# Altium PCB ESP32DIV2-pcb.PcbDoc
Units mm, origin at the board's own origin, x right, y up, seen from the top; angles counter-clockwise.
Board outline 52.58 x 99.94 mm, 2 copper layers (Top Layer, Bottom Layer); 90 components, 85 nets, 423 pads, 138 vias.
Unrouted connection lines stored in the file: 11.
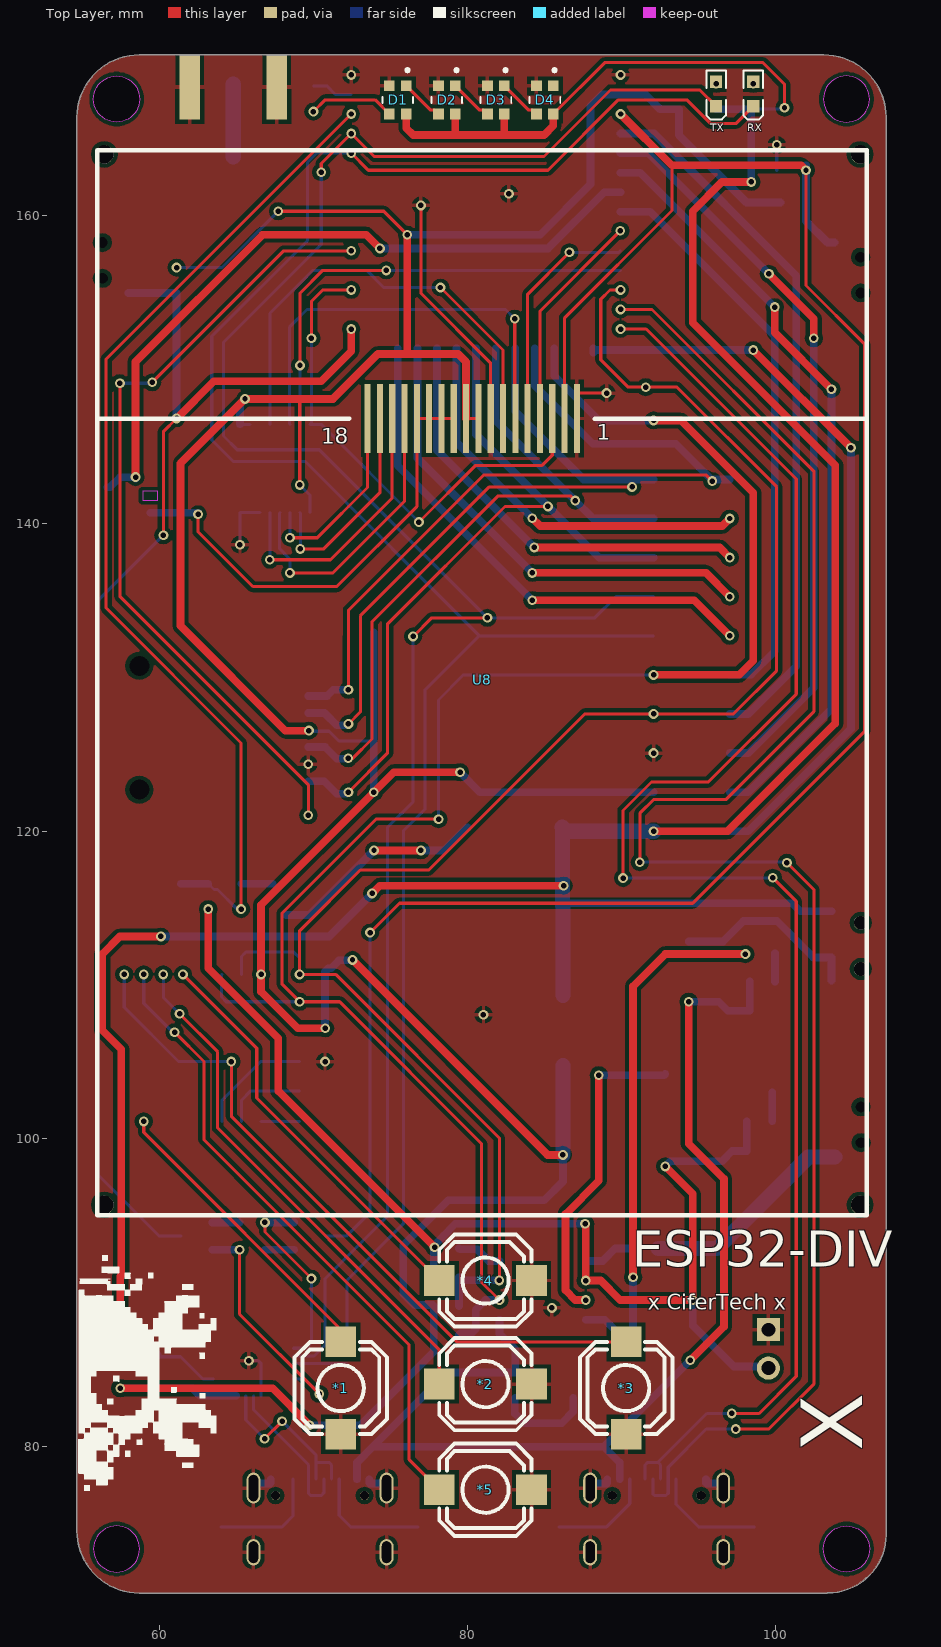
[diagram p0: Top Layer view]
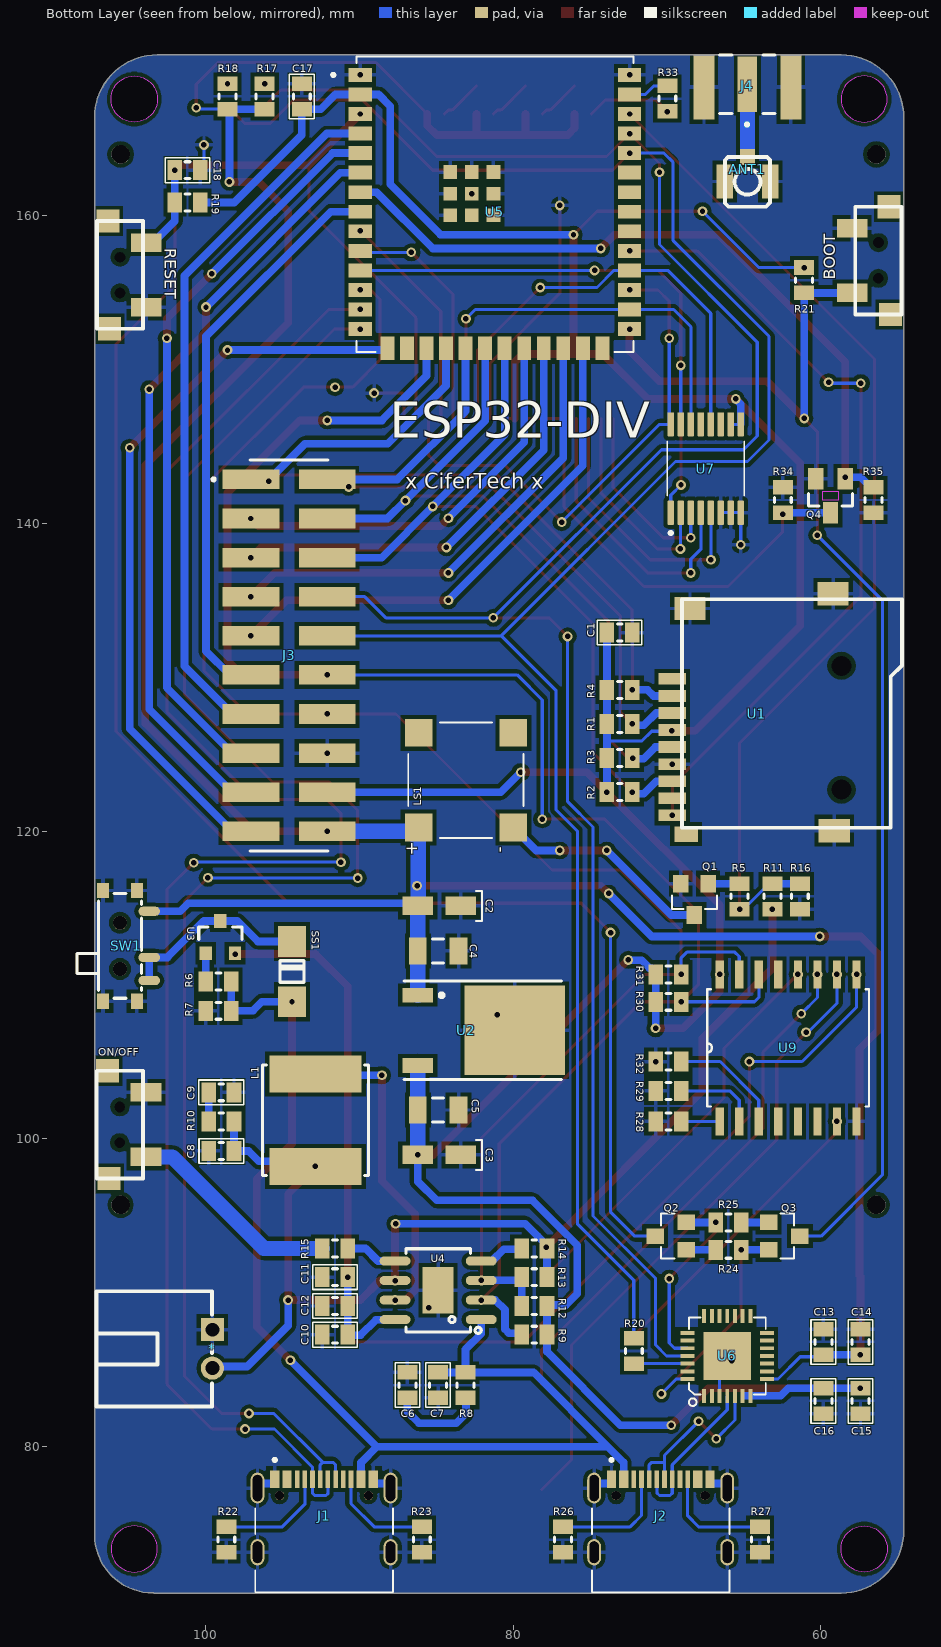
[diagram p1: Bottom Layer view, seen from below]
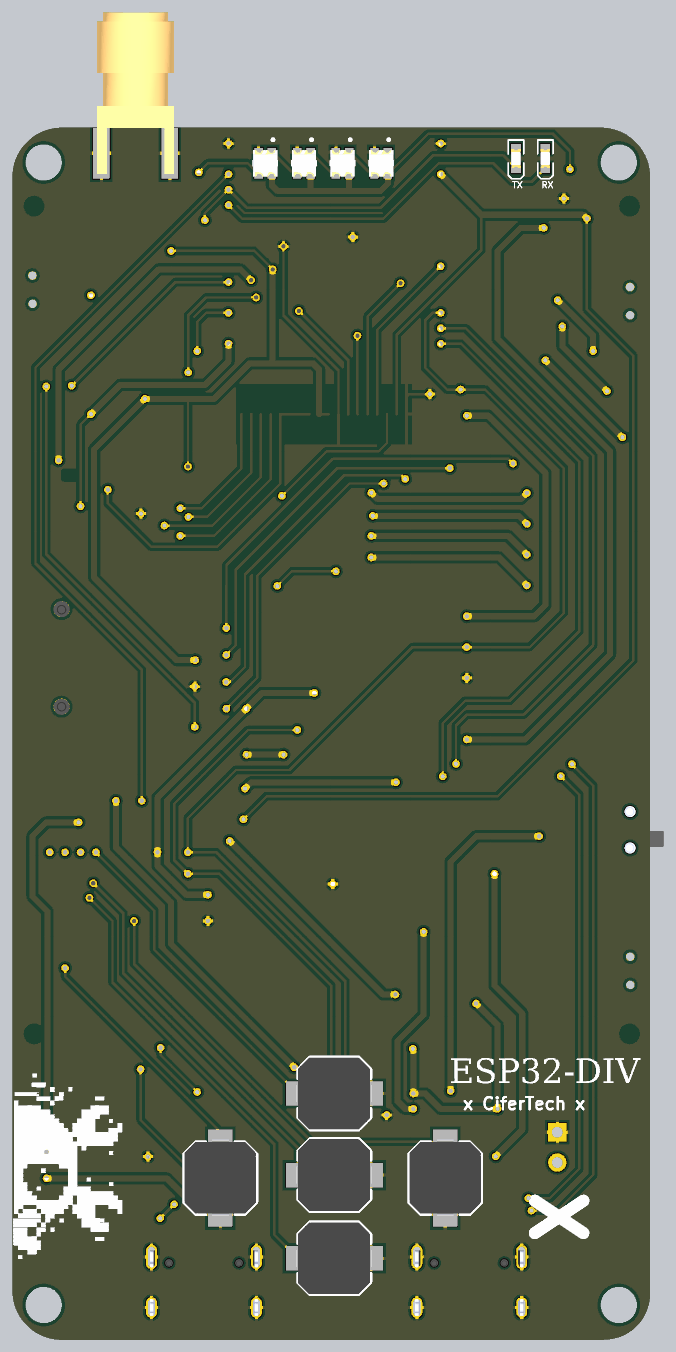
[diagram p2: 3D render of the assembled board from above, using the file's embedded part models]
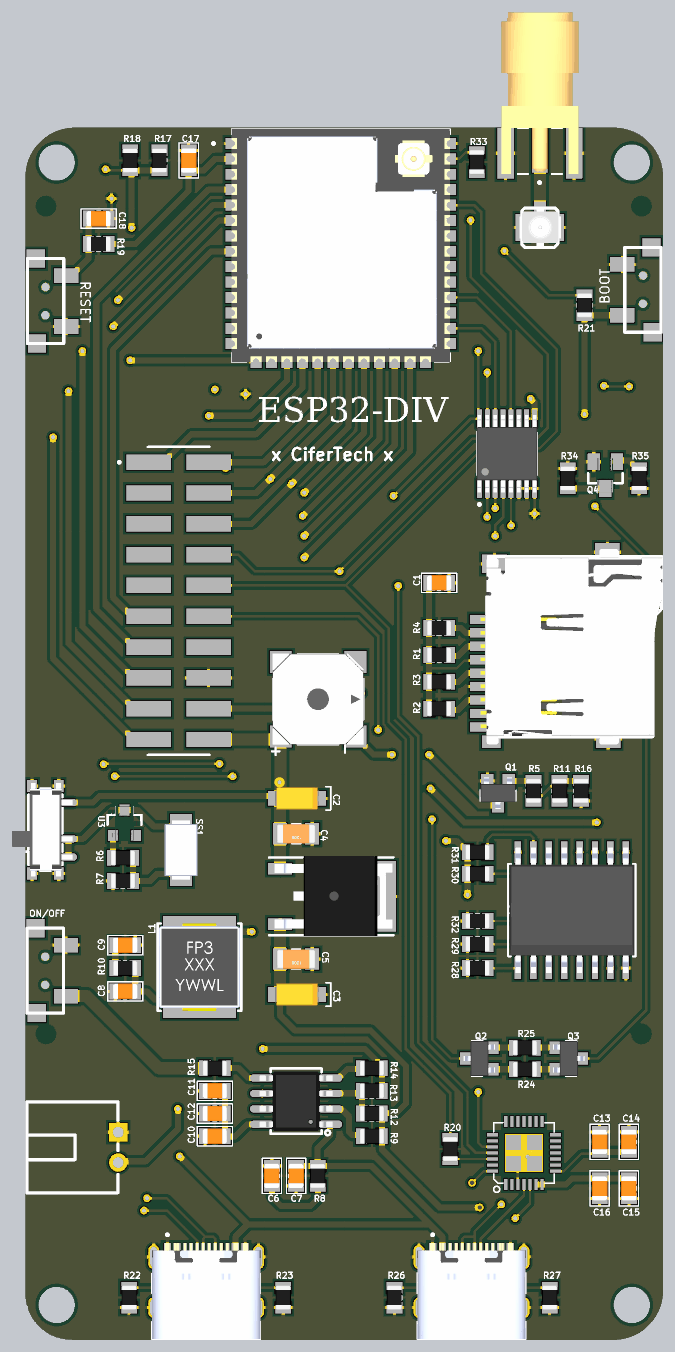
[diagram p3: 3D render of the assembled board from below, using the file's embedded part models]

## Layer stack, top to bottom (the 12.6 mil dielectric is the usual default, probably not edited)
Top Solder: solder mask 0.0102, Solder Resist, Dk 3.5
Top Layer: signal copper 0.0356
Dielectric 1: dielectric 0.32, FR-4, Dk 4.8
Bottom Layer: signal copper 0.0356
Bottom Solder: solder mask 0.0102, Solder Resist, Dk 3.5

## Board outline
58.674,70.496 cw(c58.674,74.56) 54.61,74.56 ccw(c54.356,74.56) 54.61,74.564 54.61,166.378 cw(c58.674,166.37) 58.674,170.434 ccw(c58.674,170.688) 58.677,170.434 103.12,170.434 ccw(c103.124,170.688) 103.124,170.434 cw(c103.124,166.37) 107.188,166.372 cw(c103.124,166.37) 107.188,166.37 cw(c107.442,166.37) 107.188,166.372 107.188,166.37 107.188,74.296 ccw(c107.442,74.295) 107.188,74.295 cw(c103.4,74.295) 103.4,70.508 ccw(c103.4,70.253) 103.325,70.496 94.568,70.496 67.76,70.496 58.675,70.496 ccw(c58.674,70.242)
cut-out: 57.189,74.864 ccw(c57.189,73.364) 55.689,73.364 ccw(c57.189,73.364) 57.189,71.864 ccw(c57.189,73.364) 58.689,73.364 ccw(c57.189,73.364)
cut-out: 104.609,74.864 cw(c104.609,73.364) 106.109,73.364 cw(c104.609,73.364) 104.609,71.864 cw(c104.609,73.364) 103.109,73.364 cw(c104.609,73.364)
cut-out: 104.609,166.066 ccw(c104.609,167.566) 106.109,167.566 ccw(c104.609,167.566) 104.609,169.066 ccw(c104.609,167.566) 103.109,167.566 ccw(c104.609,167.566)
cut-out: 57.189,166.066 cw(c57.189,167.566) 55.689,167.566 cw(c57.189,167.566) 57.189,169.066 cw(c57.189,167.566) 58.689,167.566 cw(c57.189,167.566)

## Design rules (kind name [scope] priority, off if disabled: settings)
Clearance [All] p1: gap=0.254 ignorepadtopadclearanceinfootprint=TRUE except(0: Arc-Hole Track-Hole SMDPad-Hole THPad-Hole Via-Hole Fill-Hole Poly-Hole Region-Hole Text-Hole)
ComponentClearance [All] p1 off: gap=-1 collisioncheckmode=3 verticalgap=2540 showdistances=FALSE
Height [All] p1: minheight=-1 maxheight=-1 prefheight=-1
PolygonConnect [All] p1: connectstyle=Relief reliefconductorwidth=0.254 reliefentries=4 polygonreliefangle="90 Angle" airgapwidth=0.254
RoomDefinition ESP32DIV2-sch [InComponentClass('ESP32DIV2-sch')] p1: confinementstyle=ConfineIn formatcopy=TRUE lockcomponents=FALSE outline 0,0 50.8,0 50.8,25.4 0,25.4
RoutingVias [All] p1: holewidth=0.711 width=1.27 viastyle="Through Hole" minholewidth=0.711 minwidth=1.27 maxholewidth=0.711 maxwidth=1.27
SolderMaskExpansion [All] p1: expansion=0.102 istentingtop=FALSE
Width [All] p1: maxlimit=1 minlimit=0.2 preferedwidth=0.5 minimp=50.000000 maximp=50.000000 favimp=50.000000
28 further rules are at their usual default settings.

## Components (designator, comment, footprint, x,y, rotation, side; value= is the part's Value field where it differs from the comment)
* "CONN-TH" PCBComponent_1#1 102.489,86.487 r270 bottom
*1 "Tactle Switch" PCBComponent_1#2 71.755,83.82 r270 top
*2 "Tactle Switch" PCBComponent_1#2 81.153,84.074 r0 top
*3 "Tactle Switch" PCBComponent_1#2 90.297,83.82 r270 top
*4 "Tactle Switch" PCBComponent_1#2 81.153,90.805 r0 top
*5 "Tactle Switch" PCBComponent_1#2 81.153,77.216 r0 top
ANT1 "ANT U.FL" "U.FL SMD" 64.768,163.006 r0 bottom
BOOT "BUTTON" "PUSH BUTTON SMD" 56.281,157.163 r180 bottom
C1 "100nf" "C 0805" 73.901,132.903 r180 bottom
C2 "Capacitor Tantalum SMD" "Tan 1206 (3216X18L) Size A" 78.058,120.602 r0 bottom value=2.2uf
C3 "Capacitor Tantalum SMD" "Tan 1206 (3216X18L) Size A" 78.057,104.426 r0 bottom value=2.2uf
C4 "10uf" "CAP 1206 (3216X15L)" 84.866,112.22 r0 bottom
C5 "10uf" "CAP 1206 (3216X15L)" 84.866,101.886 r0 bottom
C6 "10uf" "C 0805" 86.866,84.835 r270 bottom
C7 "10uf" "C 0805" 84.867,83.185 r90 bottom
C8 "10uf" "C 0805" 99.78,99.223 r180 bottom
C9 "10uf" "C 0805" 98.13,103.033 r0 bottom
C10 "22uf" "C 0805" 92.393,87.284 r180 bottom
C11 "22uf" "C 0805" 92.393,91.02 r180 bottom
C12 "22uf" "C 0805" 92.393,89.152 r180 bottom
C13 "10uf" "C 0805" 59.841,87.638 r270 bottom
C14 "100nf" "C 0805" 57.428,87.638 r270 bottom
C15 "10uf" "C 0805" 57.428,82.156 r90 bottom
C16 "100nf" "C 0805" 59.841,82.156 r90 bottom
C17 "100nf" "C 0805" 93.726,168.558 r270 bottom
C18 "100nf" "C 0805" 100.33,162.941 r0 bottom
D1 "WS2812B2020" LED_WS2812B2020 75.461,167.509 r270 top
D2 "WS2812B2020" LED_WS2812B2020 78.645,167.509 r270 top
D3 "WS2812B2020" LED_WS2812B2020 81.83,167.509 r270 top
D4 "WS2812B2020" LED_WS2812B2020 85.015,167.509 r270 top
J1 "TYPE-C-31-M-12" HRO_TYPE-C-31-M-12 92.281,73.152 r180 bottom
J2 "TYPE-C-31-M-12" HRO_TYPE-C-31-M-12 70.406,73.152 r180 bottom
J3 "TSM-110-04-S-DV" SAMTEC_TSM-110-04-S-DV 94.553,131.423 r90 bottom
J4 "SMA" SAMTEC_SMA-J-P-H-ST-EM1 64.77,168.529 r0 bottom
L1 "Inductor SMD Cored" L_57 92.837,101.219 r270 bottom
LS1 "CMT-7525-80-SMT-TR" XDCR_CMT-7525-80-SMT-TR 83.058,123.317 r90 bottom
ON/OFF "BUTTON" "PUSH BUTTON SMD" 105.537,100.838 r0 bottom (schematic designator ON/OFF1)
Q1 "S8050" SOT-23 68.216,115.57 r0 bottom
Q2 "S8050" SOT-23 69.75,93.69 r90 bottom
Q3 "S8050" SOT-23 62.384,93.69 r270 bottom
Q4 "SI2302" SOT23 59.375,141.791 r0 bottom
R1 "10k" "RES 0805 (2012X06L)" 73.901,126.965 r180 bottom
R2 "10k" "RES 0805 (2012X06L)" 73.901,122.533 r180 bottom
R3 "10k" "RES 0805 (2012X06L)" 73.901,124.749 r180 bottom
R4 "10k" "RES 0805 (2012X06L)" 73.901,129.181 r180 bottom
R5 "1k" "RES 0805 (2012X06L)" 65.294,114.936 r90 bottom
R6 "1k" "RES 0805 (2012X06L)" 98.317,110.236 r0 bottom
R7 "10k" "RES 0805 (2012X06L)" 99.967,108.331 r180 bottom
R8 "100k" "RES 0805 (2012X06L)" 83.089,83.185 r90 bottom
R9 "1k" "RES 0805 (2012X06L)" 79.44,87.284 r180 bottom
R10 "0.5R" "RES 0805 (2012X06L)" 99.779,101.145 r180 bottom
R11 "100k" "RES 0805 (2012X06L)" 63.146,116.586 r270 bottom
R12 "1k" "RES 0805 (2012X06L)" 79.44,89.152 r180 bottom
R13 "1k" "RES 0805 (2012X06L)" 79.44,91.02 r180 bottom
R14 "1k" "RES 0805 (2012X06L)" 79.44,92.889 r180 bottom
R15 "10k" "RES 0805 (2012X06L)" 90.743,92.889 r0 bottom
R16 "100k" "RES 0805 (2012X06L)" 61.368,114.936 r90 bottom
R17 "1k" "RES 0805 (2012X06L)" 96.139,166.908 r90 bottom
R18 "1k" "RES 0805 (2012X06L)" 98.552,166.908 r90 bottom
R19 "4.7k" "RES 0805 (2012X06L)" 101.976,160.841 r180 bottom
R20 "470" "RES 0805 (2012X06L)" 72.157,87.052 r270 bottom
R21 "4.7k" "RES 0805 (2012X06L)" 61.087,154.968 r90 bottom
R22 "5.1k" "RES 0805 (2012X06L)" 98.631,74.802 r270 bottom
R23 "5.1k" "RES 0805 (2012X06L)" 85.931,74.802 r270 bottom
R24 "12k" "RES 0805 (2012X06L)" 65.179,92.801 r0 bottom
R25 "12k" "RES 0805 (2012X06L)" 66.829,94.579 r180 bottom
R26 "5.1k" "RES 0805 (2012X06L)" 76.76,74.802 r270 bottom
R27 "5.1k" "RES 0805 (2012X06L)" 63.96,74.802 r270 bottom
R28 "1k" "RES 0805 (2012X06L)" 69.081,101.143 r0 bottom
R29 "1k" "RES 0805 (2012X06L)" 69.081,103.124 r0 bottom
R30 "1k" "RES 0805 (2012X06L)" 70.731,108.915 r180 bottom
R31 "1k" "RES 0805 (2012X06L)" 69.081,110.693 r0 bottom
R32 "1k" "RES 0805 (2012X06L)" 69.081,105.029 r0 bottom
R33 "1k" "RES 0805 (2012X06L)" 69.977,168.424 r270 bottom
R34 "10R" "RES 0805 (2012X06L)" 62.474,140.691 r90 bottom
R35 "10k" "RES 0805 (2012X06L)" 56.581,142.341 r270 bottom
RESET "BUTTON" "PUSH BUTTON SMD" 105.517,156.047 r0 bottom
RX "LED" LED_0603 98.552,167.894 r270 top
SS1 "1n4007" "Diode 1N4007 SMD" 91.909,105.867 r90 bottom
SW1 "SlideSwitch" SWSLIDT_SPDT_MSS3 105.537,112.546 r90 bottom
TX "LED" LED_0603 96.139,167.894 r270 top
U1 "SD CARD SPI MODE" "MICRO SD" 69.012,120.219 r90 bottom
U2 "LF33" D-PACK 86.191,109.344 r270 bottom
U3 "AO3401" SOT23-3 99.017,113.066 r180 bottom
U4 "IP5306" SO_8T 84.867,90.169 r0 bottom
U5 "ESP32-S3-WROOM-1U-N16" XCVR_ESP32-S3-WROOM-1U-N16 81.18,160.724 r180 bottom locked
U6 "CP2102" QFN28G_0.5-5X5MM 66.082,85.902 r90 bottom
U7 "XPT2046" TSSOP16 67.48,143.561 r90 bottom
U8 "2.8 240X320_ILI9341" LCDTFT_1.8IN_ST7735_18P 144.693,148.403 r180 top locked
U9 "PCF8574T" SOIC127P1032X265-16N 62.13,105.918 r90 bottom

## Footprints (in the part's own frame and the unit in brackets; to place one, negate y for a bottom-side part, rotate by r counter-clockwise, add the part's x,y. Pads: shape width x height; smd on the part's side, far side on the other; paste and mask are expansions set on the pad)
"C 0805" [mm] "CAP"
  rect 0.95x1.3 smd: 1(0,0) 2(1.65,0)
  silkscreen extent -0.63,-0.8 2.27,0.8, body extent -0.19,-0.64 1.84,0.63, height 0.65
"CAP 1206 (3216X15L)" [mm] "Chip Capacitor, 2-Leads, Body 3.2x1.6mm, IPC High Density"
  rect 1.15x1.75 smd: 1(-1.325,0) 2(1.325,0)
  silkscreen extent -0.35,-0.77 0.35,0.77, body extent -1.6,-0.8 1.6,0.8, height 1
D-PACK [mm] "D-PACK"
  rect 0.95x2 smd: 1(0,0) 3(4.57,0)
  rect 5.8x6.5 smd: 2(2.285,6.3)
  silkscreen extent -0.91,-0.9 5.49,9.35, body extent -1.03,-0.45 5.55,9.25, height 2.3
"Diode 1N4007 SMD" [mm]
  rect 2x1.8 smd: 1(3.048,2.452) 2(6.968,2.452)
  silkscreen extent 4.32,1.64 5.71,3.28, body extent 2.51,1.09 7.51,3.79, height 2.16
HRO_TYPE-C-31-M-12 [mm]
  rect 0.6x1.14 smd mask+0.05: A1_B12(-3.2,4.75) A4_B9(-2.4,4.75) B1_A12(3.2,4.75) B4_A9(2.4,4.75)
  rect 0.3x1.14 smd mask+0.05: A5(-1.25,4.75) A6(-0.25,4.75) A7(0.25,4.75) A8(1.25,4.75) B5(1.75,4.75) B6(0.75,4.75) B7(-0.75,4.75) B8(-1.75,4.75)
  oval 0.9x2 hole 0.6 slot 1.7 at 90 deg: S1(-4.325,4.17) S2(4.325,4.17)
  oval 0.9x1.7 hole 0.6 slot 1.4 at 90 deg: S3(-4.325,0) S4(4.325,0)
  round 0.6 hole 0.6 unplated: ""(-2.89,3.68) ""(2.89,3.68)
  silkscreen extent -4.47,-2.6 4.47,6.1, body extent -4.47,-2.6 4.47,5.3, height 3.31
L_57 [mm]
  rect 2.4x6 smd: 1(-3,0) 2(3,0)
  silkscreen extent -3.6,-3.45 3.6,3.45, body extent -3.62,-3.35 3.63,3.35, height 3
LCDTFT_1.8IN_ST7735_18P [mm] "LCD TFT Color, 1.8\", 128X160, ST7735 Driver"
  rect 0.4x4.5 smd: 1(57.597,1.591) 2(58.397,1.591) 3(59.197,1.591) 4(59.997,1.591) 5(60.797,1.591) 6(61.597,1.591) 7(62.397,1.591) 8(63.197,1.591) 9(63.997,1.591) 10(64.797,1.591) 11(65.597,1.591) 12(66.397,1.591) 13(67.197,1.591) 14(67.997,1.591) 15(68.797,1.591) 16(69.597,1.591) 17(70.397,1.591) 18(71.197,1.591)
  round 1.2 hole 1.2: ""(39.2,52.685) ""(39.2,-15.565) ""(88.3,52.685) ""(88.3,-15.565)
  silkscreen extent 38.74,-15.87 88.75,53.36, body extent 38.8,-17.02 88.86,53.31, height 4
LED_0603 [mm] "Chip LED, 2-Leads, Body 1.6x0.8mm, IPC Medium Density"
  rect 0.8x0.8 smd: A(-0.8,0) K(0.8,0)
  silkscreen extent -1.52,-0.64 1.65,0.64, body extent -0.8,-0.4 0.8,0.4, height 0.7
LED_WS2812B2020 [mm]
  rect 0.7x0.7 smd: 1(-0.915,0.55) 2(-0.915,-0.55) 3(0.915,-0.55) 4(0.915,0.55)
  silkscreen extent -2.03,-1 0.2,1, body extent -1.1,-1 1.1,1, height 0.84
"MICRO SD" [mil] "MICRO SD"
  rect 30x70 smd: 1(380.91,25.07) 2(337.29,25.07) 3(293.66,25.07) 4(250.04,25.07) 5(206.41,25.07) 6(162.79,25.07) 7(119.16,25.07) 8(75.54,25.07) 9(31.91,25.07)
  rect 60x80 smd: 6(-7.09,-388.93) 6(560.91,-19.93) 6(598.91,-385.93)
  rect 40x60 smd: 10(-16.09,-9.93)
  round 0 hole 51.18: ""(97.44,-407.48) ""(414.37,-407.48)
  silkscreen extent 0,-562 585,0, body extent -25,-565 609,26, height 73
PCBComponent_1#1 [mm]
  rect 1.5x1.5 hole 0.9: 1(-1.123,2.953)
  round 1.5 hole 0.9: 2(1.377,2.953)
  silkscreen extent -3.62,-4.57 3.88,2.93
PCBComponent_1#2 [mm]
  rect 2x2 smd paste+0 mask+0.051: 1(-3,0) 2(3,0)
  silkscreen extent -3,-3 3,3, body extent -3.18,-2.96 3.11,2.96, height 4.95
"PUSH BUTTON SMD" [mm]
  rect 1.5x1.5 smd: 1(0.712,3.405) 4(0.812,-3.595)
  rect 2x1.2 smd: 2(-1.688,2.005) 3(-1.688,-2.195)
  round 0 hole 0.7: ""(0.012,-1.245) ""(0.02,1.079)
  silkscreen extent -1.49,-3.6 1.51,3.4
QFN28G_0.5-5X5MM [mm]
  rect 0.9x0.254 smd: 1(-2.59,1.5) 2(-2.59,1) 3(-2.59,0.5) 4(-2.59,0) 5(-2.59,-0.5) 6(-2.59,-1) 7(-2.59,-1.5) 15(2.59,-1.5) 16(2.59,-1) 17(2.59,-0.5) 18(2.59,0) 19(2.59,0.5) 20(2.59,1) 21(2.59,1.5)
  rect 0.254x0.9 smd: 8(-1.5,-2.59) 9(-1,-2.59) 10(-0.5,-2.59) 11(0,-2.59) 12(0.5,-2.59) 13(1,-2.59) 14(1.5,-2.59) 22(1.5,2.59) 23(1,2.59) 24(0.5,2.59) 25(0,2.59) 26(-0.5,2.59) 27(-1,2.59) 28(-1.5,2.59)
  rect 3.1x3.1 smd paste-3: 29(0,0)
  silkscreen extent -3.25,-2.5 2.5,2.5
"RES 0805 (2012X06L)" [mm] "Chip Resistor, 2-Leads, Body 2.0x1.3mm, IPC High Density _ (0.100 W)"
  rect 0.95x1.3 smd: 1(0,0) 2(1.65,0)
  silkscreen extent 0.67,-0.55 0.98,0.55, body extent -0.19,-0.63 1.84,0.64, height 0.6
SAMTEC_SMA-J-P-H-ST-EM1 [mm]
  rect 1.27x3.6 smd: 1(0,0)
  rect 1.35x4.2 smd: 2_1(-2.825,0.2) 3_1(2.825,0.2)
  rect 1.35x4.2 smd far side: 2_2(-2.825,0.2) 3_2(2.825,0.2)
  silkscreen extent -1.8,-1.9 1.8,2.72, body extent -3.17,-11.42 3.18,1.91, height 3.55
SAMTEC_TSM-110-04-S-DV [mm]
  rect 1.27x3.68 smd: 01(11.43,2.475) 02(11.43,-2.475) 03(8.89,2.475) 04(8.89,-2.475) 05(6.35,2.475) 06(6.35,-2.475) 07(3.81,2.475) 08(3.81,-2.475) 09(1.27,2.475) 10(1.27,-2.475) 11(-1.27,2.475) 12(-1.27,-2.475) 13(-3.81,2.475) 14(-3.81,-2.475) 15(-6.35,2.475) 16(-6.35,-2.475) 17(-8.89,2.475) 18(-8.89,-2.475) 19(-11.43,2.475) 20(-11.43,-2.475)
  silkscreen extent -12.7,-2.54 12.7,5
SO_8T [mm] "SOP-8, 5x3.9mm body 1.27mm pitch, DDA, SO PowerPAD"
  oval 2x0.6 smd: 1(-2.8,1.905) 2(-2.8,0.635) 3(-2.8,-0.635) 4(-2.8,-1.905) 5(2.8,-1.905) 6(2.8,-0.635) 7(2.8,0.635) 8(2.8,1.905)
  rect 2x3 smd paste-3 mask+0.1: 9(0,0)
  silkscreen extent -2.8,-2.7 2.1,2.8, body extent -3,-2.45 3,2.45, height 1.7
SOIC127P1032X265-16N [mil]
  rect 71x21 smd: 1(-188,175) 2(-188,125) 3(-188,75) 4(-188,25) 5(-188,-25) 6(-188,-75) 7(-188,-125) 8(-188,-175) 9(188,-175) 10(188,-125) 11(188,-75) 12(188,-25) 13(188,25) 14(188,75) 15(188,125) 16(188,175)
  silkscreen extent -150,-207 150,207, body extent -203,-203 203,203, height 104
SOT23 [mm]
  rect 1x1.4 smd: 1(-0.95,-1.1) 2(0.95,-1.1) 3(0,1.1)
  Keep-Out Layer region: 0.5,-0.3 -0.5,-0.3 -0.5,0.3 0.5,0.3
  silkscreen extent -1.42,-0.15 1.42,0.66, body extent -1.18,-1.46 1.19,1.46, height 1.12
SOT23-3 [mm]
  rect 0.8x0.9 smd: 1(-0.95,-1) 2(0.95,-1) 3(0,1.1)
  silkscreen extent -1.4,-0.1 1.4,0.7, body extent -1.4,-1.45 1.4,1.45, height 1.25
SOT-23 [mil]
  rect 40x45 smd: 1(-35,-40) 2(35,-40) 3(0,40)
  silkscreen extent -58,-10 58,25, body extent -57,-51 57,51, height 55
SWSLIDT_SPDT_MSS3 [mm] "Switch, Slide, SPDT,"
  oval 0.6x1.4 smd: 1(2.25,-1.9) 2(-0.75,-1.9) 3(-2.25,-1.9)
  rect 1x0.8 smd: EP(-3.6,-1.1) EP(-3.6,1.1) EP(3.6,-1.1) EP(3.6,1.1)
  round 0.9 hole 0.9 unplated: ""(-1.5,0) ""(1.5,0)
  silkscreen extent -3.4,-1.4 3.4,2.8, body extent -3.85,-2.24 3.85,2.76, height 1.4
"Tan 1206 (3216X18L) Size A" [mil]
  rect 78.7x47.2 smd: 1(210,215) 2(320.22,215)
  silkscreen extent 156,177 171,253, body extent 193,179 336,250, height 71
TSSOP16 [mm]
  rrect25% 1.57x0.41 smd: 1(-2.87,2.275) 2(-2.87,1.625) 3(-2.87,0.975) 4(-2.87,0.325) 5(-2.87,-0.325) 6(-2.87,-0.975) 7(-2.87,-1.625) 8(-2.87,-2.275) 9(2.87,-2.275) 10(2.87,-1.625) 11(2.87,-0.975) 12(2.87,-0.325) 13(2.87,0.325) 14(2.87,0.975) 15(2.87,1.625) 16(2.87,2.275)
  silkscreen extent -4.29,-2.5 1.76,2.5, body extent -3.2,-2.5 3.2,2.5, height 1.1
"U.FL SMD" [mm] "U.FL Antenna-Design:Ali Hafizi"
  rect 1x1.05 smd: 1(0.002,-0.8)
  rect 1.05x2.2 smd: 2(-1.475,0.8) 2(1.475,0.8)
  silkscreen extent -1.47,-0.8 1.47,2.44, body extent -1.73,-0.76 1.67,2.34, height 1.25
XCVR_ESP32-S3-WROOM-1U-N16 [mm]
  rect 1.5x0.9 smd: 1(-8.75,8.41) 2(-8.75,7.14) 3(-8.75,5.87) 4(-8.75,4.6) 5(-8.75,3.33) 6(-8.75,2.06) 7(-8.75,0.79) 8(-8.75,-0.48) 9(-8.75,-1.75) 10(-8.75,-3.02) 11(-8.75,-4.29) 12(-8.75,-5.56) 13(-8.75,-6.83) 14(-8.75,-8.1) 27(8.75,-8.1) 28(8.75,-6.83) 29(8.75,-5.56) 30(8.75,-4.29) 31(8.75,-3.02) 32(8.75,-1.75) 33(8.75,-0.48) 34(8.75,0.79) 35(8.75,2.06) 36(8.75,3.33) 37(8.75,4.6) 38(8.75,5.87) 39(8.75,7.14) 40(8.75,8.41)
  rect 0.9x1.5 smd: 15(-6.985,-9.35) 16(-5.715,-9.35) 17(-4.445,-9.35) 18(-3.175,-9.35) 19(-1.905,-9.35) 20(-0.635,-9.35) 21(0.635,-9.35) 22(1.905,-9.35) 23(3.175,-9.35) 24(4.445,-9.35) 25(5.715,-9.35) 26(6.985,-9.35)
  rect 0.9x0.9 smd: 41_1(-2.9,2.09) 41_2(-1.5,2.09) 41_3(-0.1,2.09) 41_4(-2.9,0.69) 41_5(-1.5,0.69) 41_6(-0.1,0.69) 41_7(-2.9,-0.71) 41_8(-1.5,-0.71) 41_9(-0.1,-0.71)
  round 0 all layers, no hole mask+0: 41_10(-2.2,2.09) 41_11(-0.8,2.09) 41_12(-2.9,1.39) 41_13(-1.5,1.39) 41_14(-0.1,1.39) 41_15(-2.2,0.69) 41_16(-0.8,0.69) 41_17(-2.9,-0.01) 41_18(-1.5,-0.01) 41_19(-0.1,-0.01) 41_20(-2.2,-0.71) 41_21(-0.8,-0.71)
  silkscreen extent -10.6,-9.6 9,9.6, body extent -9,-9.6 9,9.6, height 3.35
XDCR_CMT-7525-80-SMT-TR [mm]
  rect 1.8x1.8 smd: 1(3.075,3.075) 2(3.075,-3.075) N(-3.075,-3.075) P(-3.075,3.075)
  silkscreen extent -3.75,-3.75 3.75,3.75, body extent -3.75,-3.75 3.75,3.75, height 2.5

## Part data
ANT1: "Antenna"
BOOT ON/OFF RESET: library part "PUSH BUTTON RIGHT", "PUSH BUTTON"
C1 C4 C5 C6 C7 C8 C9 C10 C11 C12 C13 C14 C15 C16 C17 C18: library part "CAP SMD", "Capacitor"
D1 D2 D3 D4: "LED; SMD; 2020; RGB; 2x2x0.84mm; 3.7Ã·5.3V; Lens: transparent; 2kHz", Package=None
J1 J2: "USB Connectors 24 Receptacle 1 8.94*7.3mm RoHS", Package=Package
J3: "Conn Unshrouded Header HDR 20 POS 2.54mm Solder ST SMD Tube", Package=None
J4: library part SMA-J-P-H-ST-EM1, "SMA Connector Jack, Female Socket 50Ohm Board Edge, End Launch Solder", Package=None
LS1: "7.5 mm, 3.6 Vo-p, 80 dB, Surface Mount (SMT), Magnetic Audio Transducer Buzzer", Package="CUI Devices"
Q1 Q2 Q3: library part SMD-TRANSISTORS-NPN-25V-500MW(SOT-23), "Bipolar (BJT) Transistor NPN 25 V 500 mA 150MHz 300 mW Surface Mount SOT-23", Package=None
Q4: "N-Channel 20 V 2.6A (Ta) 710mW (Ta) Surface Mount SOT-23-3 (TO-236)", Package="SOT-23-3 Vishay Siliconix"
R1 R2 R3 R4 R5 R6 R7 R8 R9 R10 R11 R12 R13 R14 R15 R16 R17 R18 R19 R20 R21 R22 R23 R24 R25 R26 R27 R28 R29 R30 R31 R32 R33 R34 R35: library part RES, "RESISTOR"
SS1: library part "Diode 1n4007", "Diode 1n4007"
SW1: library part SWSLIDT_SPDT_MSS3, "SWITCH, SLIDE, SPDT, SMD"
U2: "3.3V VOLTAGE REGULATOR"
U3: "P-Channel 30 V 4A (Ta) 1.4W (Ta) Surface Mount SOT-23-3", Package="SOT-23-3 Alpha &amp; Omega Semiconductor"
U4: library part IP5306_SO8T, "IC Power Bank, 2.1A charger, 2.4A discharger"
U5: "Bluetooth, WiFi 802.11b/g/n, Bluetooth v5.0 Transceiver Module 2.4GHz Antenna Not Included, U.FL Surface Mount", Package=None
U6: library part INTERFACE-CP2102-GMR(QFN28), "USB Bridge, USB to UART USB 2.0 UART Interface 28-QFN _5x5_", Package="VFQFN-28 Vishay Siliconix"
U7: "Touch Screen Controller"
U8: library part "LCD_TFT_Color_2.8 240X320_ILI9341 Driver_FLAT", "LCD TFT FULL Color 2.8 240X320  ILI9341 Driver FLAT"
U9: "I/O Expander 8 IÂ²C 100 kHz 20-SSOP", Package="SOIC-16 NXP Semiconductors"

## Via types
v1: diameter 0.635, hole 0.356, Top Layer to Bottom Layer, 138 vias

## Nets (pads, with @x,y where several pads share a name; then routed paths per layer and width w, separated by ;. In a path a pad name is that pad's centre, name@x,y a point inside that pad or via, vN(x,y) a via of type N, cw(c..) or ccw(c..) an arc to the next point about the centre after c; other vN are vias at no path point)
3v3: C1.1 C3.2 C5.2 C15.2 C16.2 C17.2 J3.18 R1.1 R2.1 R3.1 R4.1 R9.2 R12.2 R19.2 R21.2 R30.1 R31.2 U1.4 U2.3 U5.2 U6.6 U6.7 U7.1 U7.9 U7.10 U8.9 U8.10 U9.16 | length 256.9
  Top Layer w0.2: v1(67.691,160.274) 74.549,160.274 v1(76.073,158.75) ; v1(69.088,142.494) 69.088,147.955 69.215,148.082 ; U8.10 U8.9
  Top Layer w0.5: v1(57.428,83.806) 67.324,83.806 v1(69.723,81.407) ; v1(69.688,126.531) 68.16,126.531 61.341,133.35 61.341,143.891 v1(65.532,148.082) 69.215,148.082 71.247,148.082 74.168,151.003 76.073,151.003 ; v1(70.739,107.188) 68.961,107.188 66.575,109.574 v1(66.575,110.693) 66.575,115.207 v1(73.901,122.533) 75.193,123.825 v1(79.502,123.825) ; v1(72.517,111.633) 85.185,98.965 v1(86.191,98.965) ; v1(76.073,158.75) 76.073,151.003 ; U8.10 79.896,150.482 79.375,151.003 76.073,151.003
  Bottom Layer w0.2: v1(61.087,156.618) 64.035,156.618 v1(67.691,160.274) ; U7.9 U7.10 ; v1(69.088,142.494) 69.755,141.827 U7.1 ; v1(69.688,126.531) 69.727,126.492 70.993,126.492 71.628,125.857 73.901,125.857
  Bottom Layer w0.5: v1(57.428,83.806) C16.2 62.117,83.806 62.611,83.312 U6.7 64.951,83.312 ; U7.9 65.205,147.727 65.532,148.053 v1(65.532,148.082) ; v1(69.723,81.407) 73.025,81.407 77.79,86.172 R9.2 R12.2 77.734,89.208 76.565,89.208 75.819,89.955 75.819,93.091 78.74,96.012 84.963,96.012 86.191,97.24 v1(86.191,98.965) ; v1(70.739,107.188) 70.735,107.192 70.735,108.911 R30.1 R31.2 70.731,110.868 70.956,111.093 71.131,111.093 71.645,111.607 72.491,111.607 v1(72.517,111.633) ; v1(73.901,122.533) R3.1 73.901,125.857 R1.1 R4.1 C1.1 ; v1(76.073,158.75) 84.709,158.75 87.981,162.022 87.981,167.102 88.743,167.864 U5.2 91.537,167.864 92.493,166.908 C17.2 93.726,165.227 98.112,160.841 R19.2 ; v1(79.502,123.825) 80.794,122.533 J3.18
  Bottom Layer w1: v1(86.191,98.965) U2.3
+5v: C2.2 C4.2 C13.2 C14.2 D1.4 D2.4 D3.4 D4.4 J3.20 LS1.P R17.1 R18.1 SW1.1 U2.1 U6.8 | length 198.4
  Top Layer w0.2: D4.4 88.897,169.926 99.187,169.926 100.584,168.529 v1(100.584,167.005)
  Top Layer w0.5: v1(57.428,85.988) 57.428,91.066 57.497,91.134 57.497,105.825 56.261,107.061 56.261,112.014 57.404,113.157 v1(60.071,113.157) ; v1(73.787,115.951) 74.295,116.459 v1(86.233,116.459) ; D1.4 76.011,165.67 76.454,165.227 79.248,165.227 ; D2.4 79.195,165.28 79.248,165.227 ; D3.4 82.38,165.27 82.423,165.227 ; D4.4 85.565,165.829 84.963,165.227 82.423,165.227 ; v1(92.078,119.993) 96.879,119.993 103.886,127 103.886,143.764 94.615,153.035 94.615,160.274 96.52,162.179 v1(98.425,162.179) ; 79.248,165.227 82.423,165.227
  Bottom Layer w0.2: C13.2 59.977,85.852 61.341,85.852 62.791,84.402 U6.8 ; R18.1 100.487,166.908 v1(100.584,167.005)
  Bottom Layer w0.5: v1(57.428,85.988) C13.2 ; v1(60.071,113.157) 70.993,113.157 v1(73.787,115.951) ; C2.2 86.367,115.316 101.092,115.316 101.612,114.796 SW1.1 ; R17.1 R18.1@98.422,166.908 ; v1(98.425,162.179) 98.425,166.905 R18.1@98.422,166.908 ; R18.1 R18.1@98.422,166.908
  Bottom Layer w1: LS1.P LS1.P@86.162,120.213 ; U2.1@86.191,109.345 C2.2 86.162,115.17 LS1.P@86.162,120.213 ; v1(92.078,119.993) 86.382,119.993 LS1.P@86.162,120.213
ACTIVE: U6.11
Button_1: *1.1 U9.7 | length 20
  Top Layer w0.2: v1(58.955,101.143) 58.955,100.43 72.16,87.225 *1.1
Button_2: *3.1 U9.9 | length 45.8
  Top Layer w0.2: v1(64.643,105.029) 64.643,101.473 79.296,86.82 *3.1
  Bottom Layer w0.2: v1(57.685,110.693) 57.685,108.558 61.214,105.029 v1(64.643,105.029)
Button_3: *5.1 U9.10 | length 41.5
  Top Layer w0.2: v1(60.96,106.934) 62.865,105.029 62.865,99.949 76.2,86.614 76.2,79.169 *5.1
  Bottom Layer w0.2: v1(58.955,110.693) 58.955,108.812 60.833,106.934 v1(60.96,106.934)
Button_4: *2.1 U9.11 | length 34
  Top Layer w0.2: v1(61.277,108.14) 63.754,105.664 63.754,100.711 78.153,86.312 *2.1
  Bottom Layer w0.2: v1(60.225,110.693) 60.225,109.193 v1(61.277,108.14)
Button_5: *4.1 U9.12 | length 26.8
  Top Layer w0.2: v1(61.495,110.693) 66.294,105.895 66.294,102.664 *4.1
Button_6: U9.6
CC1: J2.A5 R26.1 | length 7.8
  Bottom Layer w0.2: J2.A5 71.656,75.537 72.391,74.802 R26.1
CC1-1: J1.A5 R22.1 | length 7.3
  Bottom Layer w0.2: J1.A5 93.531,76.268 94.997,74.802 R22.1
CC2: J2.B5 R27.1 | length 7.4
  Bottom Layer w0.2: R27.1 67.946,74.802 68.657,75.513 68.657,77.181 J2.B5
CC2-1: J1.B5 R23.1 | length 6.8
  Bottom Layer w0.2: R23.1 89.026,74.802 90.53,76.306 90.53,77.181 J1.B5
CLK: J3.04 R3.2 U1.5 U5.20 | length 46.9
  Top Layer w0.2: v1(72.234,124.731) 72.534,124.731 73.787,125.984 73.787,133.604 81.951,141.768 86.705,141.768 v1(86.995,141.478)
  Bottom Layer w0.5: U1.5 70.753,125.462 71.501,124.714 72.216,124.714 v1(72.234,124.731) R3.2 ; U5.20 81.815,146.658 v1(86.995,141.478) 88.16,140.313 J3.04
CS: J3.01 R4.2 U1.2 U5.18 | length 53
  Top Layer w0.2: v1(72.251,129.181) 72.251,132.703 72.263,132.715 72.263,134.366 81.026,143.129 95.504,143.129 v1(95.885,142.748)
  Bottom Layer w0.5: U1.2 70.874,128.786 71.269,129.181 v1(72.251,129.181) ; U5.18 84.355,148.944 88.138,145.161 93.515,145.161 95.823,142.853 J3.01
CTS: U6.23
D+: J2.A6 J2.B6 U6.4 | length 9.8
  Bottom Layer w0.2: U6.4 66.082,82.401 69.657,78.826 J2.B6 69.657,76.978 69.8,76.835 70.485,76.835 70.657,77.007 J2.A6
D+(ESP): J1.A6 J1.B6 U5.14 | length 105.2
  Top Layer w0.2: v1(89.93,152.624) 91.597,152.624 101.346,142.875 101.346,128.905 95.631,123.19 91.948,123.19 90.095,121.337 v1(90.095,116.953) ; v1(97.155,82.169) 98.933,82.169 101.346,84.582 101.346,115.443 v1(99.822,116.967)
  Bottom Layer w0.2: v1(90.095,116.953) 99.808,116.953 v1(99.822,116.967) ; J1.B6 91.531,78.623 91.523,78.63 91.523,78.823 91.694,78.994 92.363,78.994 ; J1.A6 92.531,78.826 92.363,78.994 ; v1(97.155,82.169) 95.538,82.169 92.363,78.994
D-: J2.A7 J2.B7 U6.5 | length 11.6
  Top Layer w0.2: v1(66.802,80.518) v1(67.945,81.661)
  Bottom Layer w0.2: U6.5 65.582,81.738 v1(66.802,80.518) ; v1(67.945,81.661) 70.156,79.45 70.156,78.994 ; J2.A7 70.156,78.994 ; J2.B7 71.157,78.826 70.989,78.994 70.156,78.994
D-(ESP): J1.A7 J1.B7 U5.13 | length 109.4
  Top Layer w0.2: v1(89.93,153.894) 91.978,153.894 102.489,143.383 102.489,127.762 96.774,122.047 92.075,122.047 91.186,121.158 v1(91.186,117.983) ; v1(97.409,81.153) 99.568,81.153 102.489,84.074 102.489,116.205 v1(100.743,117.951)
  Bottom Layer w0.2: v1(91.186,117.983) 100.711,117.983 v1(100.743,117.951) ; J1.A7 92.03,77.181 92.031,76.952 92.148,76.835 92.887,76.835 93.03,76.978 J1.B7 93.03,78.679 95.504,81.153 v1(97.409,81.153)
DCD: U6.1
DSR: U6.27
DTR: Q3.2 R24.1 U6.28 | length 15.4
  Top Layer w0.2: v1(65.179,92.801) 65.179,88.618 v1(70.358,83.439)
  Bottom Layer w0.2: U6.28 69.395,84.402 v1(70.358,83.439)
  Bottom Layer w0.5: Q3.2 v1(65.179,92.801)
GND: *1.2 *2.2 *3.2 *4.2 *5.2 *.1 ANT1.2 BOOT.2 C1.2 C2.1 C3.1 C4.1 C5.1 C6.1 C7.1 C8.1 C9.1 C10.1 C11.1 C12.1 C13.1 C14.1 C15.1 C16.1 C17.1 C18.1 D1.2 D2.2 D3.2 D4.2 J1.A1_B12 J1.B1_A12 J1.S1 J1.S2 J1.S3 J1.S4 J2.A1_B12 J2.B1_A12 J2.S1 J2.S2 J2.S3 J2.S4 J3.16 J4.2_1 J4.2_2 J4.3_1 J4.3_2 ON/OFF.3 Q1.2 Q4.2 R7.1 R16.1 R22.2 R23.2 R26.2 R27.2 R28.2 R29.2 R32.2 R34.2 R35.2 RESET.2 SW1.EP U1.6 U2.2 U4.9 U5.1 U5.40 U5.41_1 U5.41_2 U5.41_3 U5.41_4 U5.41_5 U5.41_6 U5.41_7 U5.41_8 U5.41_9 U6.3 U6.29 U7.6 U7.7 U7.8 U8.1 U8.8 U9.8 | length 33.5
  Top Layer w0.2: v1(76.962,160.655) 76.962,154.94 81.496,150.406 U8.8 ; U8.1 87.096,148.236 87.196,148.336 87.196,148.463 v1(89.027,148.463)
  Bottom Layer w0.2: v1(65.205,138.611) U7.8 U7.7 U7.6 ; v1(65.786,85.598) 66.386,85.598 66.582,85.402 U6.3 ; C18.1@100.08,162.941 v1(100.08,164.588)
  Bottom Layer w0.5: J2.S2 66.082,77.427 66.266,77.612 67.157,77.612 67.203,77.658 J2.B1_A12@67.203,77.902 ; J2.A1_B12@73.611,77.902 73.611,77.658 73.657,77.612 74.547,77.612 74.732,77.427 J2.S1 ; J1.S2 87.956,77.427 88.14,77.612 89.03,77.612 89.076,77.658 J1.B1_A12@89.076,77.902 ; J1.A1_B12@95.484,77.902 95.484,77.658 95.53,77.612 96.421,77.612 96.605,77.427 J1.S1
  other v1: 85.471,89.027 70.731,105.029 81.026,108.077 69.649,124.354 92.078,125.073 82.68,161.414 72.43,169.134 89.93,169.134
GPIO0: BOOT.3 Q3.3 R21.1 U5.27 | length 84.1
  Top Layer w0.2: v1(60.229,139.223) 60.229,145.954 v1(61.087,146.812)
  Top Layer w0.5: v1(61.087,146.812) 63.5,149.225 70.485,149.225 72.43,151.17 v1(72.43,152.624)
  Bottom Layer w0.2: v1(60.229,139.223) 56.007,135.001 56.007,97.663 59.98,93.69 Q3.3
  Bottom Layer w0.5: BOOT.3 R21.1 v1(61.087,146.812)
IO1: R33.1 U5.39 | length 2.7
  Bottom Layer w0.2: R33.1 70.844,168.424 71.404,167.864 U5.39
IO2: R5.1 R11.1 R16.2 U5.38 | length 66.5
  Top Layer w0.2: v1(65.278,114.935) 65.278,125.73 56.515,134.493 56.515,150.679 v1(72.43,166.594)
  Bottom Layer w0.2: R11.1 63.521,116.211 63.748,116.211 65.023,114.936 R5.1
  Bottom Layer w0.5: R16.2 R11.1
IO3: J3.19 U5.15 | length 48.6
  Top Layer w0.5: v1(98.552,151.257) v1(104.902,144.907)
  Bottom Layer w0.5: U5.15 88.165,151.074 88.348,151.257 v1(98.552,151.257) ; J3.19 98.233,119.993 104.902,126.662 v1(104.902,144.907)
IO4: J3.13 U5.4 | length 46.2
  Bottom Layer w0.5: U5.4 92.105,165.324 101.346,156.083 101.346,130.726 98.233,127.613 J3.13
IO5: J3.15 U5.5 | length 48.2
  Top Layer w0.5: v1(99.568,156.21) 102.489,153.289 v1(102.489,152.019)
  Bottom Layer w0.5: U5.5 91.724,164.054 v1(99.568,156.21) ; J3.15 98.233,125.073 102.489,129.329 v1(102.489,152.019)
IO6: J3.17 U5.6 | length 50.1
  Top Layer w0.5: v1(99.949,154.051) 99.949,152.4 v1(103.632,148.717)
  Bottom Layer w0.5: U5.6 91.216,162.784 v1(99.949,154.051) ; J3.17 98.233,122.533 103.632,127.932 v1(103.632,148.717)
IO7: Q4.1 R35.1 U5.7 | length 46.5
  Top Layer w0.5: v1(58.42,143.002) 58.42,150.495 66.675,158.75 73.406,158.75 v1(74.295,157.861)
  Bottom Layer w0.5: R35.1 56.756,142.341 57.417,143.002 58.314,143.002 Q4.1 ; v1(74.295,157.861) 85.217,157.861 88.87,161.514 U5.7
IO8: J3.14 R12.1 R13.1 R31.1 U4.3 U5.12 U9.15 | length 110.6
  Top Layer w0.2: v1(82.057,90.814) 82.057,100.061 71.425,110.693 v1(69.081,110.693) 69.081,113.531 73.025,117.475 77.47,117.475 87.608,127.613 v1(92.078,127.613) 97.26,127.613 100.076,130.429 100.076,142.367 93.599,148.844 v1(91.567,148.844) 90.424,148.844 88.646,150.622 88.646,154.559 89.251,155.164 v1(89.93,155.164)
  Bottom Layer w0.2: U9.15 65.305,111.86 65.587,112.141 68.707,112.141 69.081,111.767 v1(69.081,110.693)
  Bottom Layer w0.5: R12.1 R13.1 79.638,90.823 82.048,90.823 v1(82.057,90.814) U4.3
IO9: J3.12 R9.1 R30.2 U4.2 U5.17 U9.14 | length 114.2
  Top Layer w0.2: v1(78.105,120.777) 74.041,120.777 67.945,114.681 67.945,110.051 v1(69.081,108.915) 71.679,108.915 80.899,99.695 80.899,90.702 v1(82.067,89.534)
  Top Layer w0.5: v1(92.075,146.685) 93.853,146.685 98.552,141.986 98.552,131.064 97.641,130.153 v1(92.078,130.153)
  Bottom Layer w0.2: U9.14 64.008,110.666 64.008,109.22 64.313,108.915 v1(69.081,108.915) ; v1(78.105,120.777) 78.105,128.524 79.734,130.153 v1(92.078,130.153)
  Bottom Layer w0.5: R9.1 79.533,87.376 80.264,87.376 80.518,87.63 80.518,88.9 81.153,89.535 82.066,89.535 v1(82.067,89.534) ; U5.17 85.625,149.579 88.519,146.685 v1(92.075,146.685)
IO11: J3.02 R1.2 U1.3 U5.19 | length 46.4
  Top Layer w0.2: v1(72.251,126.965) 73.025,127.739 73.025,133.985 81.407,142.367 v1(90.678,142.367)
  Bottom Layer w0.5: U1.3 70.696,127.678 71.501,126.873 72.159,126.873 v1(72.251,126.965) ; U5.19 83.085,147.293 87.525,142.853 J3.02
IO13: J3.06 R2.2 U1.7 U5.21 | length 49
  Top Layer w0.2: v1(72.251,122.533) 74.803,125.085 74.803,133.477 82.423,141.097 v1(85.217,141.097)
  Bottom Layer w0.5: U1.7 70.683,123.246 71.501,122.428 72.146,122.428 v1(72.251,122.533) ; U5.21 80.545,145.769 v1(85.217,141.097) 88.541,137.773 J3.06
IO14: J3.03 U5.22 | length 26.3
  Top Layer w0.5: v1(84.201,140.335) 84.709,139.827 96.542,139.827 v1(97.028,140.313)
  Bottom Layer w0.5: U5.22 79.275,145.261 v1(84.201,140.335)
IO15: J3.11 U5.8 | length 37.4
  Bottom Layer w0.5: U5.8 91.851,160.244 99.949,152.146 99.949,131.699 98.403,130.153 J3.11
IO16: U5.9 U8.4 | length 14.4
  Top Layer w0.2: U8.4 84.696,153.784 v1(89.916,159.004)
IO17: U5.10 U8.5 | length 15.3
  Top Layer w0.2: U8.5 83.896,154.889 v1(86.614,157.607)
  Bottom Layer w0.2: v1(86.614,157.607) 89.833,157.607 U5.10
IO18: U5.11 U7.15 | length 30
  Top Layer w0.2: v1(69.105,150.258) 69.105,154.957 70.582,156.434 v1(74.706,156.434)
  Bottom Layer w0.2: U7.15 v1(69.105,150.258) ; v1(74.706,156.434) U5.11
IO21: J3.05 U5.23 | length 28.5
  Top Layer w0.5: v1(84.328,138.43) 96.371,138.43 v1(97.028,137.773)
  Bottom Layer w0.5: U5.23 78.005,144.753 v1(84.328,138.43)
IO35: U5.28 U7.14 U8.6 | length 28.2
  Top Layer w0.2: v1(83.058,153.289) 83.058,146.85 U8.6
  Bottom Layer w0.2: U7.14 68.434,146.453 68.434,152.762 69.566,153.894 U5.28 82.453,153.894 v1(83.058,153.289)
IO36: U5.29 U7.16 U8.3 | length 33.5
  Top Layer w0.2: v1(69.85,152.019) 69.85,154.432 70.582,155.164 v1(72.43,155.164) ; v1(76.835,140.081) 80.518,143.764 84.836,143.764 85.496,144.424 U8.3
  Bottom Layer w0.2: v1(69.85,152.019) 69.85,146.526 U7.16 70.485,146.431 v1(76.835,140.081)
IO37: U5.30 U7.12 U8.7 | length 30.1
  Top Layer w0.2: v1(78.232,155.321) 82.296,151.257 U8.7
  Bottom Layer w0.2: U7.12 67.155,153.642 69.947,156.434 U5.30 73.436,156.434 74.549,155.321 v1(78.232,155.321)
IO38: U1.9 U5.31 | length 51.7
  Top Layer w0.2: v1(57.404,149.098) 57.404,135.255 69.649,123.01 v1(69.649,121.029) ; v1(59.499,149.161) 68.042,157.704 v1(72.43,157.704)
  Bottom Layer w0.2: v1(57.404,149.098) 59.436,149.098 v1(59.499,149.161)
IO39: U5.32
IO47: J3.07 U5.24 | length 31.2
  Top Layer w0.5: v1(84.201,136.779) 95.482,136.779 v1(97.028,135.233)
  Bottom Layer w0.5: U5.24 76.735,144.245 v1(84.201,136.779)
IO48: J3.09 U5.25 | length 33.8
  Top Layer w0.5: v1(84.201,135.001) 94.72,135.001 v1(97.028,132.693)
  Bottom Layer w0.5: U5.25 75.465,143.737 v1(84.201,135.001)
NetANT1_1: ANT1.1 J4.1 | length 4.7
  Bottom Layer w1: ANT1.1 J4.1
NetC6_2: C6.2 R8.1 | length 6.3
  Bottom Layer w0.5: R8.1 83.058,83.154 83.058,82.169 83.693,81.534 86.106,81.534 86.868,82.296 86.868,83.183 C6.2
NetC9_2: C9.2 R10.1 | length 1.9
  Bottom Layer w0.5: R10.1 C9.2@99.78,103.032
NetD1_1: D1.1 D2.3 | length 2.8
  Top Layer w0.2: D1.1 77.591,166.844 77.845,166.844 D2.3
NetD1_3: D1.3 R33.2 | length 5.6
  Top Layer w0.2: v1(69.977,166.751) 70.739,167.513 73.992,167.513 D1.3
NetD3_1: D3.1 D4.3 | length 2.8
  Top Layer w0.2: D3.1 83.96,166.844 84.215,166.844 D4.3
NetL1_1: L1.1 U4.7 | length 20.8
  Top Layer w0.5: v1(87.667,89.534) 87.666,89.535 86.995,89.535 86.36,90.17 86.36,95.123 88.519,97.282 v1(88.519,104.14)
  Bottom Layer w0.5: v1(88.519,104.14) 92.758,104.14 L1.1
NetLS1_N: LS1.N Q1.3 | length 14.1
  Top Layer w0.5: v1(73.914,118.745) v1(76.962,118.745)
  Bottom Layer w0.5: Q1.3 69.723,114.554 v1(73.914,118.745) ; v1(76.962,118.745) 78.486,118.745 LS1.N
NetON/OFF1_2: ON/OFF.2 R15.2 | length 14
  Bottom Layer w0.5: ON/OFF.2@104.036,98.772 ON/OFF.2@104.066,98.742
  Bottom Layer w1: R15.2 96.191,92.889 102.135,98.833 ON/OFF.2
NetQ1_1: Q1.1 R5.2 | length 2
  Bottom Layer w0.5: R5.2 Q1.1
NetQ2_1: Q2.1 R24.2 | length 1.9
  Bottom Layer w0.5: R24.2 Q2.1
NetQ3_1: Q3.1 R25.2 | length 1.8
  Bottom Layer w0.5: Q3.1 R25.2
NetQ4_3: Q4.3 R34.1 U8.11 U8.12 U8.13 U8.14 | length 30.2
  Top Layer w0.2: v1(62.484,140.589) 62.484,139.446 66.04,135.89 71.501,135.89 76.696,141.085 U8.14 U8.13 U8.12 U8.11
  Bottom Layer w0.5: Q4.3 R34.1
NetR6_2: R6.2 U3.1 | length 1.8
  Bottom Layer w0.5: R6.2 U3.1
NetR14_1: R14.1 U4.4 | length 3
  Bottom Layer w0.5: R14.1 79.492,92.837 80.604,92.837 81.367,92.074 U4.4
NetR15_1: R15.1 U4.5 | length 3.4
  Bottom Layer w0.5: U4.5 U4.5 88.773,92.075 89.587,92.889 R15.1
NetR17_2: R17.2 TX.A
  other v1: 96.139,168.558
NetR18_2: R18.2 RX.A
  other v1: 98.552,168.558
NetR20_2: R20.2 U6.26 | length 3.5
  Bottom Layer w0.2: U6.26 R20.2
NetR28_1: R28.1 U9.1 | length 2.5
  Bottom Layer w0.2: U9.1 R28.1
NetR29_1: R29.1 U9.2 | length 5.4
  Bottom Layer w0.2: U9.2 65.305,102.516 65.913,103.124 R29.1
NetR32_1: R32.1 U9.3 | length 7.5
  Bottom Layer w0.2: U9.3 64.035,102.516 66.548,105.029 R32.1
NetSS1_2: SS1.2 SW1.2 SW1.3 U3.3 | length 12.3
  Bottom Layer w0.5: SS1.2 96.593,112.835 97.924,114.166 U3.3 100.083,114.166 102.453,111.796 SW1.2 SW1.3
RESET: C18.2 Q2.3 R19.1 RESET.3 U5.3 U8.2 | length 136.2
  Top Layer w0.2: v1(73.66,113.411) 75.565,115.316 94.615,115.316 105.791,126.492 105.791,151.638 101.976,155.453 v1@101.976,162.945 ; U8.2 86.296,153.352 93.27,160.326 93.27,163.254
  Top Layer w0.5: v1(89.93,166.594) 93.27,163.254 101.667,163.254 v1@101.976,162.945
  Bottom Layer w0.2: Q2.3 72.1,93.69 73.66,95.25 v1(73.66,113.411)
  Bottom Layer w0.5: C18.2@101.976,163.254 R19.1 101.976,159.644 103.378,158.242 RESET.3
  other v1: 101.98,162.941
RI: U6.2
RTS: Q2.2 R25.1 U6.24 | length 12.3
  Top Layer w0.2: v1(66.829,94.579) 66.829,93.953 v1(69.85,90.932)
  Bottom Layer w0.2: U6.24 69.511,86.402 69.85,86.741 v1(69.85,90.932)
  Bottom Layer w0.5: v1(66.829,94.579) Q2.2
RX_0: J3.10 R20.1 RX.K U5.36 | length 136.9
  Top Layer w0.2: v1(72.43,164.054) 73.543,162.941 85.217,162.941 89.789,167.513 94.234,167.513 95.758,165.989 97.447,165.989 RX.K
  Bottom Layer w0.2: v1(72.43,164.054) 70.201,164.054 69.596,163.449 69.596,158.369 63.373,152.146 63.373,145.415 64.77,144.018 69.447,144.018 80.761,132.704 77.216,129.159 77.216,121.412 75.819,120.015 75.819,94.488 72.157,90.826 R20.1 72.184,87.052 R20.1@72.517,87.385 ; 80.772,132.693 J3.10
TX_0: J3.08 TX.K U5.37 U6.25 | length 139.1
  Top Layer w0.2: v1(70.485,162.814) 70.485,163.379 v1(72.43,165.324) 73.924,163.83 84.963,163.83 89.281,168.148 95.085,168.148 TX.K ; v1(76.454,132.651) 77.66,133.858 v1(81.28,133.858)
  Bottom Layer w0.2: U6.25 70.027,85.902 70.739,86.614 70.739,90.932 74.803,94.996 74.803,120.269 76.454,121.92 v1(76.454,132.651) ; v1(70.485,162.814) 70.485,158.115 64.135,151.765 64.135,145.669 65.024,144.78 70.358,144.78 v1(81.28,133.858) 88.265,133.858 89.64,135.233 J3.08
VBAT: *.2 C8.2 L1.2 R10.2 R11.2 R13.2 R14.2 U4.6 | length 76.5
  Top Layer w0.5: v1(63.146,114.936) 63.146,111.098 67.691,106.553 67.691,103.124 v1(77.851,92.964) ; v1(87.63,94.488) 87.667,94.451 v1(87.667,90.804) 88.647,90.804 89.916,89.535 v1(94.615,89.535) 94.615,96.441 v1(92.837,98.219)
  Bottom Layer w0.5: R13.2 R14.2 77.79,93.064 78.406,93.679 78.406,93.692 79.202,94.488 v1(87.63,94.488) ; v1(92.837,98.219) 93.17,98.552 96.52,98.552 97.191,99.223 C8.2 R10.2 ; v1(94.615,89.535) 94.615,87.884 97.282,85.217 99.43,85.217 *.2
VUPS: C10.2 C11.2 C12.2 U3.2 U4.8 | length 34.3
  Top Layer w0.5: v1(90.743,91.02) 90.743,109.92 92.837,112.014 v1(98.044,112.014)
  Bottom Layer w0.5: U4.8 88.901,88.264 89.916,87.249 90.709,87.249 C10.2 C12.2 v1(90.743,91.02)
VUSB: C7.2 J1.A4_B9 J1.B4_A9 J2.A4_B9 J2.B4_A9 R6.1 R7.2 R8.2 SS1.1 U4.1 | length 76.1
  Top Layer w0.5: v1(94.361,108.915) 94.361,99.695 96.647,97.409 96.647,87.807 v1(94.463,85.623)
  Bottom Layer w0.5: J2.A4_B9 72.807,78.976 73.839,80.008 ; U4.1 82.067,87.351 83.089,86.329 R8.2 ; C7.2 R8.2 ; J1.B4_A9 89.88,78.976 88.848,80.008 ; v1(94.361,108.915) 96.317,108.915 96.901,108.331 R7.2 R6.1 ; v1(94.463,85.623) 88.848,80.008 ; 73.839,80.008 78.666,84.835 R8.2 ; 73.839,80.008 88.848,80.008
WSD: D2.1 D3.3 | length 2.8
  Top Layer w0.2: D2.1 80.775,166.844 81.03,166.844 D3.3
X+: U7.4 U8.15 | length 19
  Top Layer w0.2: v1(68.453,136.779) 71.247,136.779 75.896,141.428 U8.15
  Bottom Layer w0.2: U7.4 67.782,140.667 67.782,138.339 68.453,137.668 v1(68.453,136.779)
X-: U7.2 U8.17 | length 13.9
  Top Layer w0.2: v1(69.124,138.339) 70.648,138.339 74.296,141.987 U8.17
  Bottom Layer w0.2: U7.2 69.124,140.672 v1(69.124,138.339)
Y+: U7.3 U8.18 | length 12.5
  Top Layer w0.2: v1(68.453,139.065) 70.231,139.065 73.496,142.33 U8.18
  Bottom Layer w0.2: v1(68.453,139.065) v1(68.453,139.065) 68.454,140.69 U7.3
Y-: U7.5 U8.16 | length 17.8
  Top Layer w0.2: v1(67.147,137.632) 71.084,137.632 75.096,141.644 U8.16
  Bottom Layer w0.2: v1(67.147,137.632) 67.151,137.636 67.151,140.687 U7.5
pads on no net: BOOT. BOOT.1 BOOT.4 D4.1 J1. J1.A8 J1.B8 J2. J2.A8 J2.B8 LS1.1 LS1.2 ON/OFF. ON/OFF.1 ON/OFF.4 RESET. RESET.1 RESET.4 SW1. U1. U1.1 U1.8 U1.10 U5.16 U5.26 U5.33 U5.34 U5.35 U5.41_10 U5.41_11 U5.41_12 U5.41_13 U5.41_14 U5.41_15 U5.41_16 U5.41_17 U5.41_18 U5.41_19 U5.41_20 U5.41_21 U6.9 U6.10 U6.12 U6.13 U6.14 U6.15 U6.16 U6.17 U6.18 U6.19 U6.20 U6.21 U6.22 U7.11 U7.13 U8. U9.4 U9.5 U9.13

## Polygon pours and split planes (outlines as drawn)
GND on Top Layer "GND_L01_P000" (solid, pour order 0): 58.674,70.496 cw(c58.674,74.56) 54.61,74.56 ccw(c54.356,74.56) 54.61,74.564 54.61,166.378 cw(c58.674,166.37) 58.674,170.434 ccw(c58.674,170.688) 58.677,170.434 103.12,170.434 ccw(c103.124,170.688) 103.124,170.434 cw(c103.124,166.37) 107.188,166.372 cw(c103.124,166.37) 107.188,166.37 cw(c107.442,166.37) 107.188,166.372 107.188,166.37 107.188,74.296 ccw(c107.442,74.295) 107.188,74.295 cw(c103.4,74.295) 103.4,70.508 ccw(c103.4,70.253) 103.325,70.496 94.568,70.496 67.76,70.496 58.675,70.496 ccw(c58.674,70.242)
GND on Bottom Layer "GND_L02_P001" (solid, pour order 1): 58.674,70.496 cw(c58.674,74.56) 54.61,74.56 ccw(c54.356,74.56) 54.61,74.564 54.61,166.378 cw(c58.674,166.37) 58.674,170.434 ccw(c58.674,170.688) 58.677,170.434 103.12,170.434 ccw(c103.124,170.688) 103.124,170.434 cw(c103.124,166.37) 107.188,166.372 cw(c103.124,166.37) 107.188,166.37 cw(c107.442,166.37) 107.188,166.372 107.188,166.37 107.188,74.296 ccw(c107.442,74.295) 107.188,74.295 cw(c103.4,74.295) 103.4,70.508 ccw(c103.4,70.253) 103.325,70.496 94.568,70.496 67.76,70.496 58.675,70.496 ccw(c58.674,70.242)

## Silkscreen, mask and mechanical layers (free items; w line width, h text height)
Top Overlay:
  drawing of 1336 lines, arcs and shapes, not listed
  text "ESP32-DIV" at 90.678,90.932 h4
  text "x CiferTech x" at 91.694,88.9 h1
  text "X" at 105.622,83.472 h4 r90
Bottom Overlay:
  text "ESP32-DIV" at 88.011,144.78 h4
  text "x CiferTech x" at 86.995,142.24 h1
Mechanical 1:
  lines w0.254: 54.23,173.101 54.228,173.609 ; 55.752,173.867 54.229,173.355 ; 55.754,172.851 54.229,173.355 ; 60.96,170.688 68.453,170.688 68.58,170.815 ; 72.748,173.399 54.229,173.355 ; 88.796,173.438 107.315,173.482 ; 105.79,173.986 107.315,173.482 ; 105.792,172.97 107.315,173.482 ; 107.316,173.228 107.314,173.736 ; 109.855,71.882 110.363,70.358 ; 109.855,169.291 110.363,170.815 ; 110.109,70.358 110.617,70.358 ; 110.109,170.815 110.617,170.815 ; 110.363,111.928 110.363,70.358 ; 110.363,129.245 110.363,170.815 ; 110.871,71.882 110.363,70.358 ; 110.871,169.291 110.363,170.815 ; 92.013,118.723 97.093,118.723 97.093,144.123 92.013,144.123 92.013,118.723
  lines w0.508: 54.356,166.37 cw(c58.674,166.37) 58.674,170.688 103.124,170.688 cw(c103.124,166.37) 107.442,166.37 107.442,73.533 ; 54.356,166.624 54.356,74.56 ccw(c58.674,74.56) 58.674,70.242 67.76,70.242 94.568,70.242 103.4,70.242 ; 103.4,70.253 ccw(c103.4,74.295) 107.442,74.295
  text "53.086 (mm)" at 73.004,172.486 h1.52 r0.14
  text "100.457 (mm)" at 111.277,112.182 h1.52 r90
